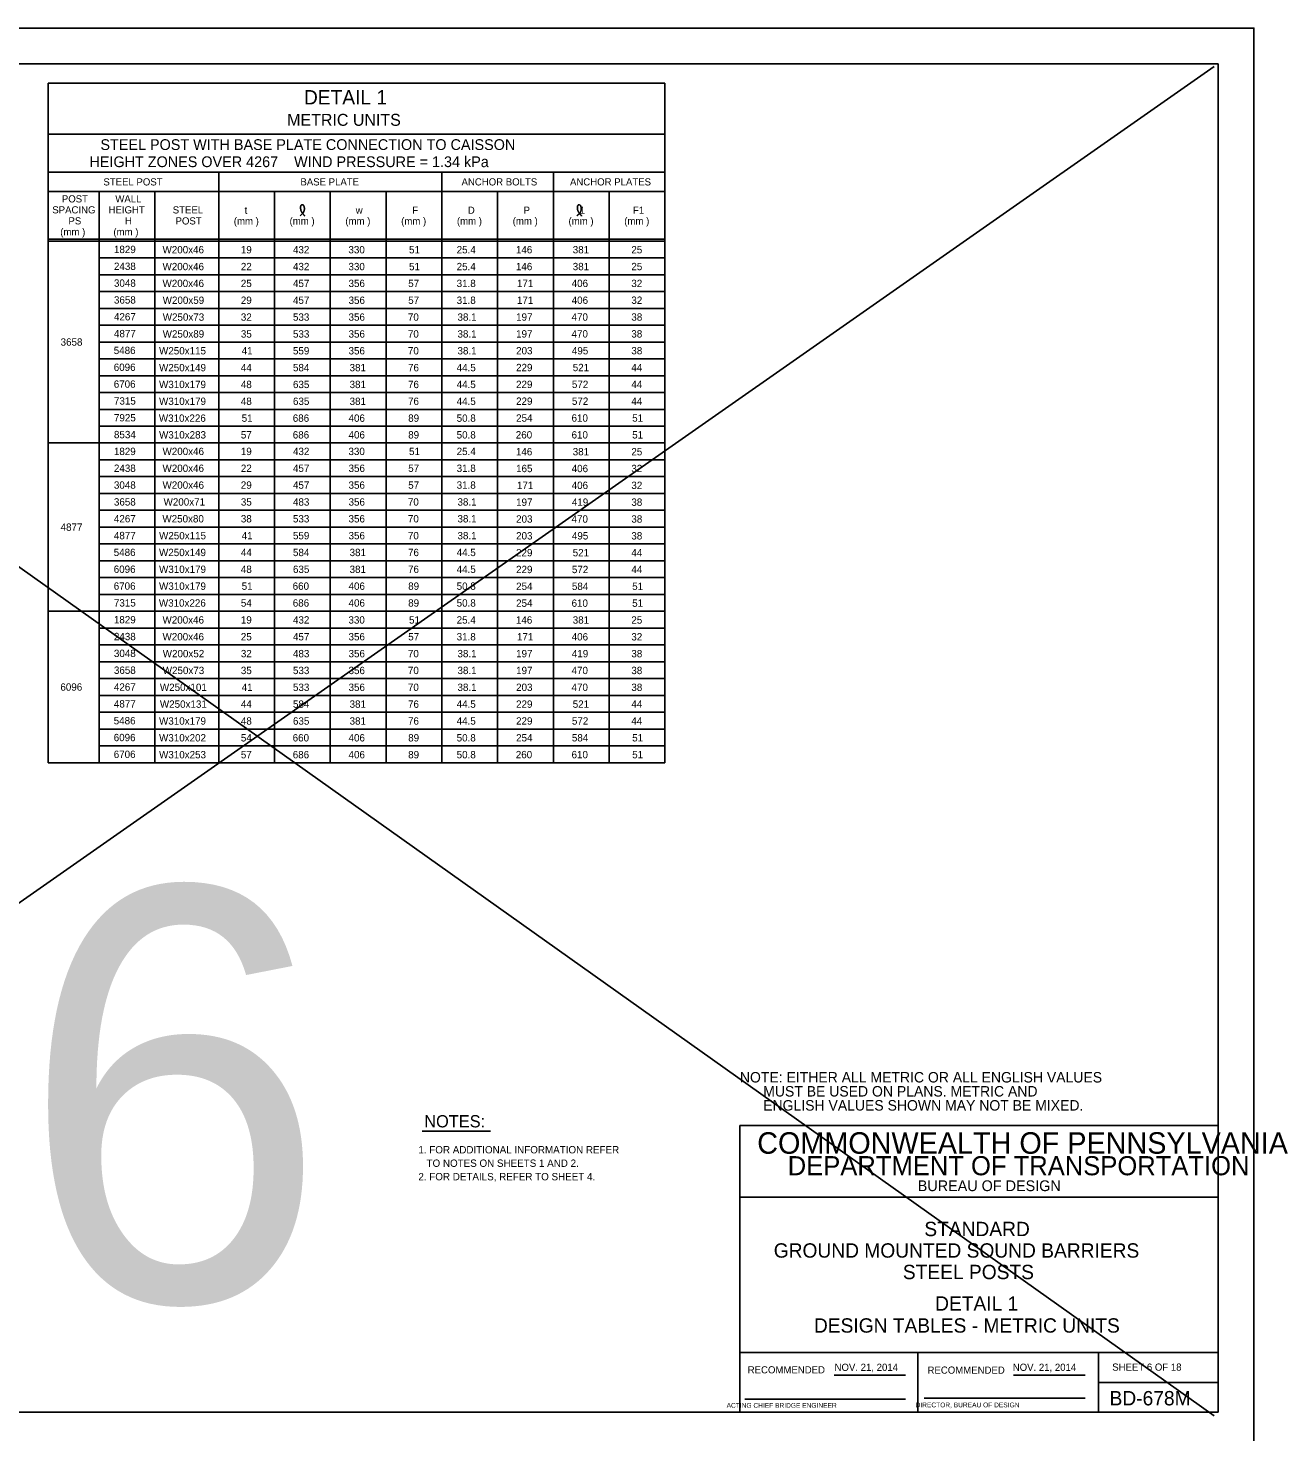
# Model space of a CAD drawing. Extents: x 3475 to 6558, y -3780 to 1166.
# Drawn here: x 5772 to 6299, y -610 to -22 of the extents above; entities that cross this region are included whole.
import ezdxf

# ---------------------------------------------------------------- set-up
doc = ezdxf.new("R2010")
doc.units = 0
for name, color, linetype in [('1', 7, 'Continuous'), ('2', 7, 'Continuous'), ('PLT-BNDY', 7, 'Continuous')]:
    doc.layers.add(name, color=color, linetype=linetype)

msp = doc.modelspace()

# ---------------------------------------------------------------- linework, layer by layer
at = {"layer": '1'}
for p, q in [((5463.42, -31.57), (6267.74, -602.77)), ((6267.74, -38.38), (5472.5, -594.82)), ((5780, -45.3), (5780, -329.63)), ((6038.01, -45.3), (5780, -45.3)), ((6038.01, -45.3), (6038.01, -329.63)), ((6038.01, -66.64), (5780, -66.64)), ((5780, -82.64), (6038.01, -82.64)), ((5851.34, -82.64), (5851.34, -329.63)), ((5944.67, -82.64), (5944.67, -329.63)), ((5991.34, -82.64), (5991.34, -329.63)), ((5780, -90.64), (6038.01, -90.64)), ((5801.34, -329.63), (5801.34, -90.64)), ((5824.67, -90.64), (5824.67, -329.63)), ((5874.67, -90.64), (5874.67, -329.63)), ((5898.01, -90.64), (5898.01, -329.63)), ((5921.34, -90.64), (5921.34, -329.63)), ((5968.01, -90.64), (5968.01, -329.63)), ((6014.67, -90.64), (6014.67, -329.63)), ((5780, -110.64), (6038.01, -110.64)), ((5780, -111.39), (6038.01, -111.39)), ((5801.34, -118.43), (6038.01, -118.43)), ((5801.34, -125.47), (6038.01, -125.47)), ((5801.34, -132.51), (6038.01, -132.51)), ((5801.34, -139.55), (6038.01, -139.55)), ((5801.34, -146.59), (6038.01, -146.59)), ((5801.34, -153.63), (6038.01, -153.63)), ((5801.34, -160.67), (6038.01, -160.67)), ((5801.34, -167.71), (6038.01, -167.71)), ((5801.34, -174.75), (6038.01, -174.75)), ((5801.34, -181.79), (6038.01, -181.79)), ((5801.34, -188.83), (6038.01, -188.83)), ((5780, -195.87), (6038.01, -195.87)), ((5801.34, -202.91), (6038.01, -202.91)), ((5801.34, -209.95), (6038.01, -209.95)), ((5801.34, -216.99), (6038.01, -216.99)), ((5801.34, -224.03), (6038.01, -224.03)), ((5801.34, -231.07), (6038.01, -231.07)), ((5801.34, -238.11), (6038.01, -238.11)), ((5801.34, -245.15), (6038.01, -245.15)), ((5801.34, -252.19), (6038.01, -252.19)), ((5801.34, -259.23), (6038.01, -259.23)), ((5780, -266.27), (6038.01, -266.27)), ((5801.34, -273.31), (6038.01, -273.31)), ((5801.34, -280.35), (6038.01, -280.35)), ((5801.34, -287.39), (6038.01, -287.39)), ((5801.34, -294.43), (6038.01, -294.43)), ((5801.34, -301.47), (6038.01, -301.47)), ((5801.34, -308.51), (6038.01, -308.51)), ((5801.34, -315.55), (6038.01, -315.55)), ((5801.34, -322.59), (6038.01, -322.59)), ((5780, -329.63), (6038.01, -329.63)), ((5936.47, -483.77), (5965.04, -483.77))]:
    msp.add_line(p, q, dxfattribs=at)
for points in [[(5885.4, -100.81), (5885.6, -100.64), (5885.72, -100.51), (5885.93, -100.31), (5886.08, -100.14), (5886.36, -99.94), (5886.56, -99.68), (5886.74, -99.49), (5886.86, -99.26), (5886.97, -99), (5887.04, -98.77), (5887.13, -98.54), (5887.15, -98.35), (5887.19, -98.1), (5887.2, -97.88), (5887.19, -97.63), (5887.14, -97.38), (5887.09, -97.14), (5887.03, -96.91), (5886.94, -96.68), (5886.87, -96.54), (5886.78, -96.44), (5886.68, -96.35), (5886.58, -96.26), (5886.47, -96.2), (5886.39, -96.18), (5886.22, -96.18), (5886.12, -96.2), (5885.98, -96.26), (5885.88, -96.34), (5885.82, -96.42), (5885.76, -96.54), (5885.68, -96.66), (5885.65, -96.8), (5885.61, -96.91), (5885.58, -97.15), (5885.55, -97.32), (5885.58, -97.51), (5885.58, -97.71), (5885.61, -97.98), (5885.64, -98.22), (5885.67, -98.38), (5885.75, -98.6), (5885.84, -98.83), (5885.94, -99.03), (5886.04, -99.22), (5886.16, -99.45), (5886.35, -99.63), (5886.47, -99.84), (5886.61, -100), (5886.72, -100.18), (5886.86, -100.35), (5886.99, -100.52), (5887.1, -100.63), (5887.21, -100.76), (5887.32, -100.93)], [(6001.2, -100.81), (6001.41, -100.64), (6001.53, -100.51), (6001.74, -100.31), (6001.89, -100.14), (6002.17, -99.94), (6002.37, -99.68), (6002.55, -99.49), (6002.67, -99.26), (6002.78, -99), (6002.85, -98.77), (6002.94, -98.54), (6002.96, -98.35), (6003, -98.1), (6003.01, -97.88), (6003, -97.63), (6002.95, -97.38), (6002.9, -97.14), (6002.84, -96.91), (6002.75, -96.68), (6002.68, -96.54), (6002.58, -96.44), (6002.49, -96.35), (6002.39, -96.26), (6002.28, -96.2), (6002.2, -96.18), (6002.03, -96.18), (6001.93, -96.2), (6001.78, -96.26), (6001.69, -96.34), (6001.63, -96.42), (6001.56, -96.54), (6001.49, -96.66), (6001.46, -96.8), (6001.42, -96.91), (6001.38, -97.15), (6001.36, -97.32), (6001.38, -97.51), (6001.38, -97.71), (6001.42, -97.98), (6001.44, -98.22), (6001.48, -98.38), (6001.56, -98.6), (6001.65, -98.83), (6001.75, -99.03), (6001.84, -99.22), (6001.96, -99.45), (6002.16, -99.63), (6002.28, -99.84), (6002.42, -100), (6002.52, -100.18), (6002.67, -100.35), (6002.8, -100.52), (6002.91, -100.63), (6003.02, -100.76), (6003.13, -100.93)]]:
    msp.add_spline(points, degree=3, dxfattribs=at)
at = {"layer": '2'}
for p, q in [((5483.34, -37.31), (6269.34, -37.31)), ((6269.34, -37.31), (6269.34, -601.31)), ((6269.34, -481.31), (6069.34, -481.31)), ((6069.34, -481.31), (6069.34, -601.31)), ((6269.34, -601.31), (6269.34, -481.31)), ((6269.34, -511.31), (6069.34, -511.31)), ((6269.34, -576.31), (6069.34, -576.31)), ((6143.84, -601.31), (6143.84, -576.31)), ((6219.34, -576.31), (6219.34, -601.31)), ((6108.81, -585.81), (6138.57, -585.81)), ((6183.81, -585.81), (6213.71, -585.81)), ((6219.34, -588.81), (6269.34, -588.81)), ((6071.34, -595.81), (6138.57, -595.81)), ((6146.47, -595.43), (6213.71, -595.43)), ((6269.34, -601.31), (5483.34, -601.31)), ((6069.34, -601.31), (6269.34, -601.31))]:
    msp.add_line(p, q, dxfattribs=at)
at = {"layer": 'PLT-BNDY'}
msp.add_lwpolyline([(5443.34, -22.31), (6284.34, -22.31), (6284.34, -616.31), (5443.34, -616.31)], close=True, dxfattribs=at)

# ---------------------------------------------------------------- texts
at = {"layer": '1'}
for s, height, p in [('DETAIL 1', 6, (5886.99, -54.25)), ('METRIC UNITS', 5.0001, (5879.97, -63.19)), ('STEEL POST WITH BASE PLATE CONNECTION TO CAISSON', 4.5001, (5801.86, -73.3)), ('HEIGHT ZONES OVER 4267    WIND PRESSURE = 1.34 kPa', 4.5001, (5797.27, -80.47)), ('STEEL POST', 3, (5803.11, -88.14)), ('BASE PLATE', 3, (5885.51, -88.14)), ('ANCHOR BOLTS', 3, (5952.91, -88.14)), ('ANCHOR PLATES', 3, (5998.28, -88.14)), ('POST', 3, (5785.73, -95.24)), ('WALL', 3, (5808.09, -95.24)), ('SPACING', 3, (5781.73, -99.84)), ('HEIGHT', 3, (5805.26, -99.84)), ('STEEL', 3, (5832.11, -99.86)), ('t', 3, (5862.17, -100)), ('w', 3, (5908.65, -100)), ('F', 3, (5932.26, -100)), ('D', 3, (5955.54, -100)), ('P', 3, (5978.87, -100)), (' 1', 3, (6001.27, -100)), ('F1', 3, (6024.61, -100)), ('PS', 3, (5788.49, -104.44)), ('H', 3, (5812.14, -104.44)), ('POST', 3, (5833.28, -104.46)), ('(mm )', 3, (5857.65, -104.5)), ('(mm )', 3, (5880.98, -104.5)), ('(mm )', 3, (5904.31, -104.5)), ('(mm )', 3, (5927.65, -104.5)), ('(mm )', 3, (5950.98, -104.5)), ('(mm )', 3, (5974.31, -104.5)), ('(mm )', 3, (5997.65, -104.5)), ('(mm )', 3, (6020.98, -104.5)), ('(mm )', 3, (5785.06, -109.04)), ('(mm )', 3, (5807.29, -109.04)), ('1829', 3.07, (5807.51, -116.44)), ('W200x46', 3.07, (5827.84, -116.55)), ('19', 3.07, (5860.59, -116.55)), ('432', 3.07, (5882.4, -116.55)), ('330', 3.07, (5905.6, -116.55)), ('51', 3.07, (5930.95, -116.55)), ('25.4', 3.07, (5950.87, -116.55)), ('146', 3.07, (5975.65, -116.55)), ('381', 3.07, (5999.42, -116.55)), ('25', 3.07, (6023.94, -116.55)), ('2438', 3.07, (5807.52, -123.48)), ('W200x46', 3.07, (5827.84, -123.6)), ('22', 3.07, (5860.6, -123.6)), ('432', 3.07, (5882.4, -123.6)), ('330', 3.07, (5905.6, -123.6)), ('51', 3.07, (5930.95, -123.6)), ('25.4', 3.07, (5950.87, -123.6)), ('146', 3.07, (5975.65, -123.59)), ('381', 3.07, (5999.42, -123.59)), ('25', 3.07, (6023.94, -123.59)), ('3048', 3.07, (5807.52, -130.52)), ('W200x46', 3.07, (5827.84, -130.64)), ('25', 3.07, (5860.6, -130.64)), ('457', 3.07, (5882.4, -130.64)), ('356', 3.07, (5905.65, -130.64)), ('57', 3.07, (5930.6, -130.64)), ('31.8', 3.07, (5950.87, -130.64)), ('171', 3.07, (5976.08, -130.63)), ('406', 3.07, (5998.98, -130.63)), ('32', 3.07, (6023.94, -130.63)), ('3658', 3.07, (5807.52, -137.56)), ('W200x59', 3.07, (5827.91, -137.69)), ('29', 3.07, (5860.59, -137.69)), ('457', 3.07, (5882.4, -137.69)), ('356', 3.07, (5905.65, -137.69)), ('57', 3.07, (5930.6, -137.69)), ('31.8', 3.07, (5950.87, -137.69)), ('171', 3.07, (5976.08, -137.67)), ('406', 3.07, (5998.98, -137.67)), ('32', 3.07, (6023.94, -137.67)), ('4267', 3.07, (5807.52, -144.6)), ('W250x73', 3.07, (5827.93, -144.73)), ('32', 3.07, (5860.6, -144.73)), ('533', 3.07, (5882.4, -144.73)), ('356', 3.07, (5905.65, -144.73)), ('70', 3.07, (5930.47, -144.73)), ('38.1', 3.07, (5951.22, -144.73)), ('197', 3.07, (5975.73, -144.71)), ('470', 3.07, (5998.93, -144.71)), ('38', 3.07, (6023.94, -144.71)), ('3658', 3.07, (5785.2, -155.16)), ('4877', 3.07, (5807.52, -151.64)), ('W250x89', 3.07, (5827.91, -151.78)), ('35', 3.07, (5860.6, -151.78)), ('533', 3.07, (5882.4, -151.78)), ('356', 3.07, (5905.65, -151.78)), ('70', 3.07, (5930.47, -151.78)), ('38.1', 3.07, (5951.22, -151.78)), ('197', 3.07, (5975.73, -151.75)), ('470', 3.07, (5998.93, -151.75)), ('38', 3.07, (6023.94, -151.75)), ('5486', 3.07, (5807.43, -158.68)), ('W250x115', 3.07, (5826.39, -158.82)), ('41', 3.07, (5860.95, -158.82)), ('559', 3.07, (5882.39, -158.82)), ('356', 3.07, (5905.65, -158.82)), ('70', 3.07, (5930.47, -158.82)), ('38.1', 3.07, (5951.22, -158.82)), ('203', 3.07, (5975.73, -158.79)), ('495', 3.07, (5999.07, -158.79)), ('38', 3.07, (6023.94, -158.79)), ('6096', 3.07, (5807.43, -165.72)), ('W250x149', 3.07, (5826.38, -165.87)), ('44', 3.07, (5860.6, -165.87)), ('584', 3.07, (5882.4, -165.87)), ('381', 3.07, (5906.08, -165.87)), ('76', 3.07, (5930.52, -165.87)), ('44.5', 3.07, (5950.87, -165.87)), ('229', 3.07, (5975.72, -165.83)), ('521', 3.07, (5999.42, -165.83)), ('44', 3.07, (6023.94, -165.83)), ('6706', 3.07, (5807.43, -172.76)), ('W310x179', 3.07, (5826.38, -172.91)), ('48', 3.07, (5860.6, -172.91)), ('635', 3.07, (5882.4, -172.91)), ('381', 3.07, (5906.08, -172.91)), ('76', 3.07, (5930.52, -172.91)), ('44.5', 3.07, (5950.87, -172.91)), ('229', 3.07, (5975.72, -172.87)), ('572', 3.07, (5999.07, -172.87)), ('44', 3.07, (6023.94, -172.87)), ('7315', 3.07, (5807.52, -179.8)), ('W310x179', 3.07, (5826.38, -179.95)), ('48', 3.07, (5860.6, -179.95)), ('635', 3.07, (5882.4, -179.95)), ('381', 3.07, (5906.08, -179.95)), ('76', 3.07, (5930.52, -179.95)), ('44.5', 3.07, (5950.87, -179.95)), ('229', 3.07, (5975.72, -179.91)), ('572', 3.07, (5999.07, -179.91)), ('44', 3.07, (6023.94, -179.91)), ('7925', 3.07, (5807.52, -186.84)), ('W310x226', 3.07, (5826.31, -187)), ('51', 3.07, (5860.95, -187)), ('686', 3.07, (5882.31, -187)), ('406', 3.07, (5905.65, -187)), ('89', 3.07, (5930.59, -187)), ('50.8', 3.07, (5950.87, -187)), ('254', 3.07, (5975.73, -186.95)), ('610', 3.07, (5998.93, -186.95)), ('51', 3.07, (6024.29, -186.95)), ('8534', 3.07, (5807.52, -193.88)), ('W310x283', 3.07, (5826.39, -193.99)), ('57', 3.07, (5860.6, -193.99)), ('686', 3.07, (5882.31, -193.99)), ('406', 3.07, (5905.65, -193.99)), ('89', 3.07, (5930.59, -193.99)), ('50.8', 3.07, (5950.87, -193.99)), ('260', 3.07, (5975.6, -193.99)), ('610', 3.07, (5998.93, -193.99)), ('51', 3.07, (6024.29, -193.99)), ('1829', 3.07, (5807.49, -200.92)), ('W200x46', 3.07, (5827.84, -200.92)), ('19', 3.07, (5860.59, -200.92)), ('432', 3.07, (5882.4, -200.92)), ('330', 3.07, (5905.6, -200.92)), ('51', 3.07, (5930.95, -200.92)), ('25.4', 3.07, (5950.87, -200.92)), ('146', 3.07, (5975.65, -201.03)), ('381', 3.07, (5999.42, -201.03)), ('25', 3.07, (6023.94, -201.03)), ('2438', 3.07, (5807.5, -207.96)), ('W200x46', 3.07, (5827.84, -207.97)), ('22', 3.07, (5860.6, -207.97)), ('457', 3.07, (5882.4, -207.97)), ('356', 3.07, (5905.65, -207.97)), ('57', 3.07, (5930.6, -207.97)), ('31.8', 3.07, (5950.87, -207.97)), ('165', 3.07, (5975.73, -208.07)), ('406', 3.07, (5998.98, -208.07)), ('32', 3.07, (6023.94, -208.07)), ('3048', 3.07, (5807.5, -215)), ('W200x46', 3.07, (5827.84, -215.01)), ('29', 3.07, (5860.59, -215.01)), ('457', 3.07, (5882.4, -215.01)), ('356', 3.07, (5905.65, -215.01)), ('57', 3.07, (5930.6, -215.01)), ('31.8', 3.07, (5950.87, -215.01)), ('171', 3.07, (5976.08, -215.11)), ('406', 3.07, (5998.98, -215.11)), ('32', 3.07, (6023.94, -215.11)), ('3658', 3.07, (5807.5, -222.04)), ('W200x71', 3.07, (5828.28, -222.06)), ('35', 3.07, (5860.6, -222.06)), ('483', 3.07, (5882.4, -222.06)), ('356', 3.07, (5905.65, -222.06)), ('70', 3.07, (5930.47, -222.06)), ('38.1', 3.07, (5951.22, -222.06)), ('197', 3.07, (5975.73, -222.15)), ('419', 3.07, (5999.06, -222.15)), ('38', 3.07, (6023.94, -222.15)), ('4267', 3.07, (5807.5, -229.08)), ('W250x80', 3.07, (5827.79, -229.1)), ('38', 3.07, (5860.6, -229.1)), ('533', 3.07, (5882.4, -229.1)), ('356', 3.07, (5905.65, -229.1)), ('70', 3.07, (5930.47, -229.1)), ('38.1', 3.07, (5951.22, -229.1)), ('203', 3.07, (5975.73, -229.19)), ('470', 3.07, (5998.93, -229.19)), ('38', 3.07, (6023.94, -229.19)), ('4877', 3.07, (5785.2, -232.6)), ('4877', 3.07, (5807.5, -236.12)), ('W250x115', 3.07, (5826.39, -236.15)), ('41', 3.07, (5860.95, -236.15)), ('559', 3.07, (5882.39, -236.15)), ('356', 3.07, (5905.65, -236.15)), ('70', 3.07, (5930.47, -236.15)), ('38.1', 3.07, (5951.22, -236.15)), ('203', 3.07, (5975.73, -236.23)), ('495', 3.07, (5999.07, -236.23)), ('38', 3.07, (6023.94, -236.23)), ('5486', 3.07, (5807.42, -243.16)), ('W250x149', 3.07, (5826.38, -243.19)), ('44', 3.07, (5860.6, -243.19)), ('584', 3.07, (5882.4, -243.19)), ('381', 3.07, (5906.08, -243.19)), ('76', 3.07, (5930.52, -243.19)), ('44.5', 3.07, (5950.87, -243.19)), ('229', 3.07, (5975.72, -243.27)), ('521', 3.07, (5999.42, -243.27)), ('44', 3.07, (6023.94, -243.27)), ('6096', 3.07, (5807.42, -250.2)), ('W310x179', 3.07, (5826.38, -250.23)), ('48', 3.07, (5860.6, -250.23)), ('635', 3.07, (5882.4, -250.23)), ('381', 3.07, (5906.08, -250.23)), ('76', 3.07, (5930.52, -250.23)), ('44.5', 3.07, (5950.87, -250.23)), ('229', 3.07, (5975.72, -250.31)), ('572', 3.07, (5999.07, -250.31)), ('44', 3.07, (6023.94, -250.31)), ('6706', 3.07, (5807.42, -257.24)), ('W310x179', 3.07, (5826.38, -257.28)), ('51', 3.07, (5860.95, -257.28)), ('660', 3.07, (5882.27, -257.28)), ('406', 3.07, (5905.65, -257.28)), ('89', 3.07, (5930.59, -257.28)), ('50.8', 3.07, (5950.87, -257.28)), ('254', 3.07, (5975.73, -257.35)), ('584', 3.07, (5999.07, -257.35)), ('51', 3.07, (6024.29, -257.35)), ('7315', 3.07, (5807.5, -264.28)), ('W310x226', 3.07, (5826.31, -264.32)), ('54', 3.07, (5860.6, -264.32)), ('686', 3.07, (5882.31, -264.32)), ('406', 3.07, (5905.65, -264.32)), ('89', 3.07, (5930.59, -264.32)), ('50.8', 3.07, (5950.87, -264.32)), ('254', 3.07, (5975.73, -264.39)), ('610', 3.07, (5998.93, -264.39)), ('51', 3.07, (6024.29, -264.39)), ('1829', 3.07, (5807.49, -271.32)), ('W200x46', 3.07, (5827.84, -271.41)), ('19', 3.07, (5860.59, -271.41)), ('432', 3.07, (5882.4, -271.41)), ('330', 3.07, (5905.6, -271.41)), ('51', 3.07, (5930.95, -271.41)), ('25.4', 3.07, (5950.87, -271.41)), ('146', 3.07, (5975.65, -271.43)), ('381', 3.07, (5999.42, -271.43)), ('25', 3.07, (6023.94, -271.43)), ('2438', 3.07, (5807.5, -278.36)), ('W200x46', 3.07, (5827.84, -278.45)), ('25', 3.07, (5860.6, -278.45)), ('457', 3.07, (5882.4, -278.45)), ('356', 3.07, (5905.65, -278.45)), ('57', 3.07, (5930.6, -278.45)), ('31.8', 3.07, (5950.87, -278.45)), ('171', 3.07, (5976.08, -278.47)), ('406', 3.07, (5998.98, -278.47)), ('32', 3.07, (6023.94, -278.47)), ('3048', 3.07, (5807.5, -285.4)), ('W200x52', 3.07, (5827.93, -285.5)), ('32', 3.07, (5860.6, -285.5)), ('483', 3.07, (5882.4, -285.5)), ('356', 3.07, (5905.65, -285.5)), ('70', 3.07, (5930.47, -285.5)), ('38.1', 3.07, (5951.22, -285.5)), ('197', 3.07, (5975.73, -285.51)), ('419', 3.07, (5999.06, -285.51)), ('38', 3.07, (6023.94, -285.51)), ('3658', 3.07, (5807.5, -292.44)), ('W250x73', 3.07, (5827.93, -292.54)), ('35', 3.07, (5860.6, -292.54)), ('533', 3.07, (5882.4, -292.54)), ('356', 3.07, (5905.65, -292.54)), ('70', 3.07, (5930.47, -292.54)), ('38.1', 3.07, (5951.22, -292.54)), ('197', 3.07, (5975.73, -292.55)), ('470', 3.07, (5998.93, -292.55)), ('38', 3.07, (6023.94, -292.55)), ('6096', 3.07, (5785.11, -299.48)), ('4267', 3.07, (5807.5, -299.48)), ('W250x101', 3.07, (5826.74, -299.59)), ('41', 3.07, (5860.95, -299.59)), ('533', 3.07, (5882.4, -299.59)), ('356', 3.07, (5905.65, -299.59)), ('70', 3.07, (5930.47, -299.59)), ('38.1', 3.07, (5951.22, -299.59)), ('203', 3.07, (5975.73, -299.59)), ('470', 3.07, (5998.93, -299.59)), ('38', 3.07, (6023.94, -299.59)), ('4877', 3.07, (5807.5, -306.52)), ('W250x131', 3.07, (5826.74, -306.63)), ('44', 3.07, (5860.6, -306.63)), ('584', 3.07, (5882.4, -306.63)), ('381', 3.07, (5906.08, -306.63)), ('76', 3.07, (5930.52, -306.63)), ('44.5', 3.07, (5950.87, -306.63)), ('229', 3.07, (5975.72, -306.63)), ('521', 3.07, (5999.42, -306.63)), ('44', 3.07, (6023.94, -306.63)), ('5486', 3.07, (5807.42, -313.56)), ('W310x179', 3.07, (5826.38, -313.68)), ('48', 3.07, (5860.6, -313.68)), ('635', 3.07, (5882.4, -313.68)), ('381', 3.07, (5906.08, -313.68)), ('76', 3.07, (5930.52, -313.68)), ('44.5', 3.07, (5950.87, -313.68)), ('229', 3.07, (5975.72, -313.67)), ('572', 3.07, (5999.07, -313.67)), ('44', 3.07, (6023.94, -313.67)), ('6096', 3.07, (5807.42, -320.6)), ('W310x202', 3.07, (5826.39, -320.72)), ('54', 3.07, (5860.6, -320.72)), ('660', 3.07, (5882.27, -320.72)), ('406', 3.07, (5905.65, -320.72)), ('89', 3.07, (5930.59, -320.72)), ('50.8', 3.07, (5950.87, -320.72)), ('254', 3.07, (5975.73, -320.71)), ('584', 3.07, (5999.07, -320.71)), ('51', 3.07, (6024.29, -320.71)), ('6706', 3.07, (5807.42, -327.64)), ('W310x253', 3.07, (5826.39, -327.77)), ('57', 3.07, (5860.6, -327.77)), ('686', 3.07, (5882.31, -327.77)), ('406', 3.07, (5905.65, -327.77)), ('89', 3.07, (5930.59, -327.77)), ('50.8', 3.07, (5950.87, -327.77)), ('260', 3.07, (5975.6, -327.75)), ('610', 3.07, (5998.93, -327.75)), ('51', 3.07, (6024.29, -327.75)), ('6', 172.8, (5768.24, -554.8)), ('NOTES:', 5.117, (5937.31, -482.15)), ('1. FOR ADDITIONAL INFORMATION REFER', 3.072, (5934.86, -493.03)), ('   TO NOTES ON SHEETS 1 AND 2.', 3.072, (5934.86, -498.66)), ('2. FOR DETAILS, REFER TO SHEET 4.', 3.072, (5934.86, -504.29)), ('STANDARD', 6, (6146.48, -527.64)), ('GROUND MOUNTED SOUND BARRIERS', 6.0001, (6083.5, -536.64)), ('STEEL POSTS', 6.0001, (6137.5, -545.64)), ('DETAIL 1', 6, (6151, -558.81)), ('DESIGN TABLES - METRIC UNITS', 6.0001, (6100.31, -568.01)), ('SHEET 6 OF 18', 3, (6225.09, -583.92)), ('BD-678M', 6, (6223.97, -598.43))]:
    msp.add_text(s, height=height, dxfattribs=at).set_placement(p)
at = {"layer": '2'}
for s, height, p in [('NOTE: EITHER ALL METRIC OR ALL ENGLISH VALUES', 4.375, (6069.34, -463.37)), ('      MUST BE USED ON PLANS. METRIC AND', 4.375, (6069.34, -469.24)), ('      ENGLISH VALUES SHOWN MAY NOT BE MIXED.', 4.375, (6069.34, -475.12)), ('COMMONWEALTH OF PENNSYLVANIA', 9, (6076.59, -493.18)), ('DEPARTMENT OF TRANSPORTATION', 8.0002, (6089.34, -502.18)), ('BUREAU OF DESIGN', 4.5, (6143.72, -508.81)), ('NOV. 21, 2014', 3, (6108.94, -584)), ('NOV. 21, 2014', 3, (6183.48, -584)), ('       ACTING CHIEF BRIDGE ENGINEER', 2.0002, (6058.43, -599.43))]:
    msp.add_text(s, height=height, dxfattribs=at).set_placement(p)
for s, height, p in [('RECOMMENDED', 3, (6072.61, -585.06)), ('RECOMMENDED', 3, (6147.83, -585.18)), ('   DIRECTOR, BUREAU OF DESIGN', 2.0002, (6140.54, -599.25))]:
    msp.add_text(s, height=height, rotation=360, dxfattribs=at).set_placement(p)

doc.saveas('drawing.dxf')
